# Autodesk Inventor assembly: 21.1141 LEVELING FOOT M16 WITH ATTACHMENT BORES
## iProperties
Created: 2007-03
Part Number: 21.1141 LEVELING FOOT M16 WITH ATTACHMENT BORES
Document SubType Name: Assembly
Designer: Andy Moles
Mass: 485.293 g
Surface Area: 370.802 cm^2
Volume: 159.503 cm^3
Density: 3.04253 g/cm^3
Author: Andy Moles
